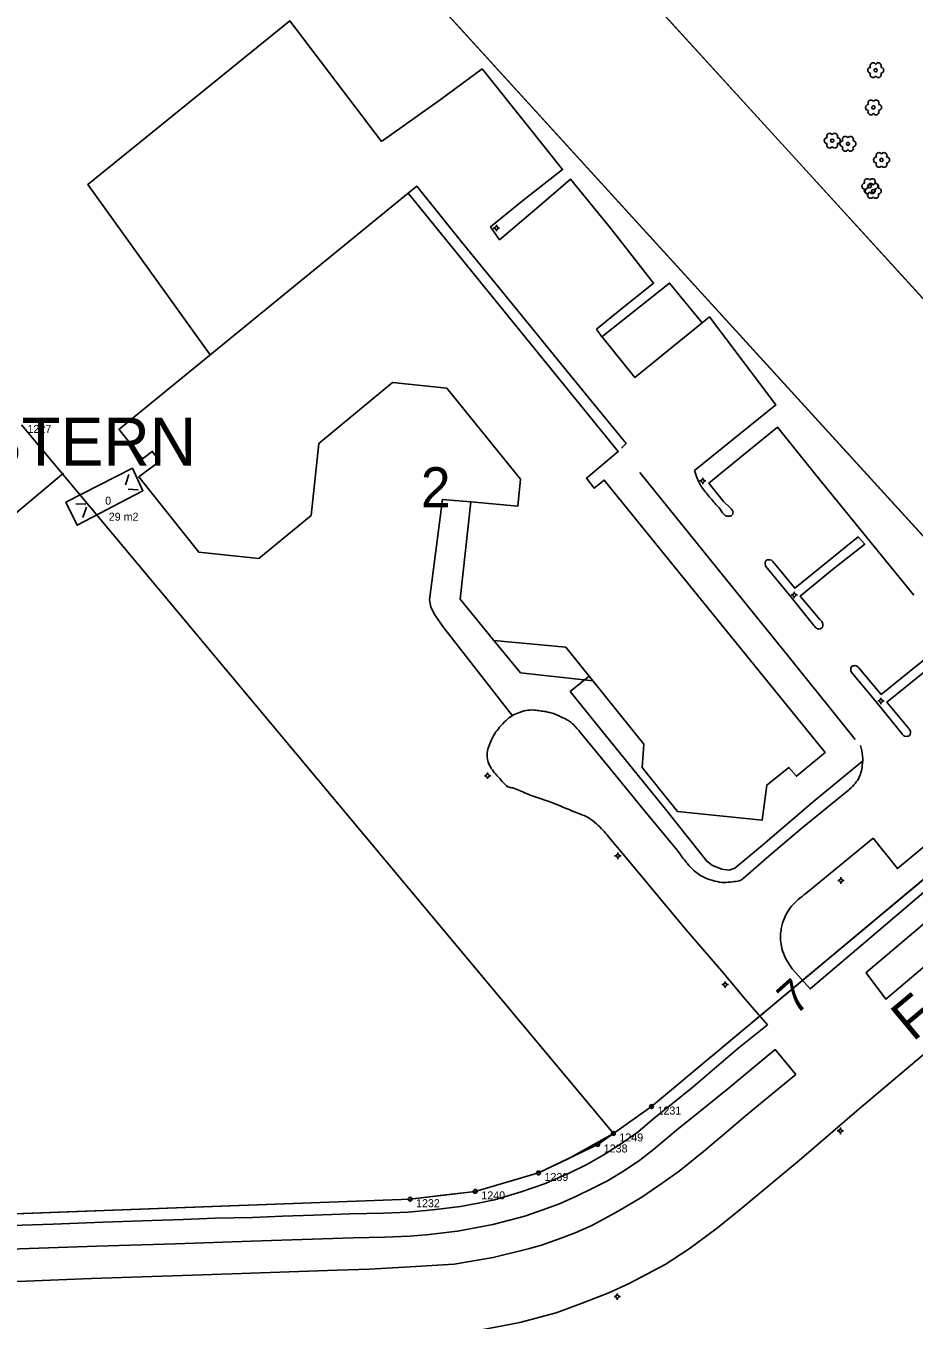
# Model space of a CAD drawing. Extents: x 1517478 to 1518189, y 6494860 to 6495389.
# Drawn here: x 1517920.3 to 1518031.3, y 6494945.7 to 6495107.4 of the extents above; entities that cross this region are included whole.
import ezdxf

# ---------------------------------------------------------------- set-up
doc = ezdxf.new("R2010")
doc.units = 0
for name, color, linetype in [('adress', 7, 'Continuous'), ('allmanbygg_symbollinje', 7, 'Continuous'), ('allmanbyggnad', 7, 'Continuous'), ('allmanbyggnad_nummer', 7, 'Continuous'), ('byggnad_areatext', 7, 'Continuous'), ('fastighetsbeteckning', 7, 'Continuous'), ('gatunamn', 7, 'Continuous'), ('gc_vag', 7, 'Continuous'), ('grans', 7, 'Continuous'), ('granspunkt', 7, 'Continuous'), ('granspunkt_text', 7, 'Continuous'), ('kvartersgrans', 7, 'Continuous'), ('kvartersgrans_utan_fastgr', 7, 'Continuous'), ('kvartersnamn', 7, 'Continuous'), ('kvartersytor', 7, 'Continuous'), ('lovtrad', 7, 'Continuous'), ('parkeringskant', 7, 'Continuous'), ('planteringskant', 7, 'Continuous'), ('rattighet_grans_ANV_EJ', 7, 'Continuous'), ('stolpe_belysning', 7, 'Continuous'), ('trappa_byggnad', 7, 'Continuous'), ('uthus', 7, 'Continuous'), ('vagkant', 7, 'Continuous'), ('vagkant_mindre', 7, 'Continuous')]:
    doc.layers.add(name, color=color, linetype=linetype)

msp = doc.modelspace()

# ---------------------------------------------------------------- linework, layer by layer
at = {"layer": 'allmanbygg_symbollinje'}
for p, q in [((1517933.16, 6495051.39), (1517932.74, 6495050.08)), ((1517933.04, 6495049.54), (1517934.3, 6495049.48)), ((1517926.51, 6495047.74), (1517927.77, 6495047.68)), ((1517927.83, 6495047.32), (1517927.41, 6495046))]:
    msp.add_line(p, q, dxfattribs=at)
at = {"layer": 'allmanbyggnad'}
for points in [[(1517931.88, 6495057.02), (1517968.08, 6495086.54), (1517994.34, 6495054.25), (1517990.35, 6495050.91), (1517991.33, 6495049.66), (1517992.59, 6495050.68), (1518020.21, 6495016.65), (1518016.6, 6495013.68), (1518015.65, 6495014.78), (1518012.9, 6495012.57), (1518012.33, 6495008.18), (1518001.72, 6495009.28), (1517997.31, 6495014.75), (1517997.53, 6495017.68), (1517987.77, 6495029.81), (1517978.76, 6495030.65), (1517974.55, 6495035.81), (1517975.91, 6495047.99), (1517981.76, 6495047.42), (1517982.09, 6495050.79), (1517972.88, 6495062.16), (1517966.11, 6495062.88), (1517956.9, 6495055.28), (1517955.93, 6495046.27), (1517949.41, 6495040.9), (1517941.88, 6495041.67), (1517934.38, 6495051.09), (1517937.03, 6495053.07), (1517936.06, 6495054.26), (1517934.86, 6495053.33), (1517931.87, 6495057.03)], [(1517925.25, 6495047.92), (1517933.58, 6495052.17), (1517934.9, 6495049.36), (1517926.69, 6495045.04), (1517925.25, 6495047.92)]]:
    msp.add_lwpolyline(points, dxfattribs=at)
at = {"layer": 'gc_vag'}
for points in [[(1517981.09, 6495021.24), (1517972.4, 6495032.38), (1517971.41, 6495033.86), (1517970.92, 6495034.79), (1517970.73, 6495035.72), (1517972.34, 6495048.28), (1517975.91, 6495047.99)], [(1518018.32, 6494987.11), (1518024.97, 6494992.73), (1518033.63, 6495000.09), (1518042.48, 6495007.51), (1518049.18, 6495012.98)], [(1518025.3, 6494989.09), (1518035.06, 6494997.36), (1518042.35, 6495003.28), (1518049.31, 6495009.27)], [(1518013.01, 6494982.59), (1518009.23, 6494979.59), (1518003.7, 6494974.86), (1518000.89, 6494972.62), (1517998.86, 6494970.97), (1517996.76, 6494969.18), (1517994.49, 6494967.61), (1517992.45, 6494966.34)], [(1518004.36, 6494971.67), (1518008.04, 6494974.61), (1518013.96, 6494979.52), (1518016.53, 6494976.42)], [(1517982.65, 6494958.71), (1517984.89, 6494959.48), (1517986.99, 6494960.25), (1517989.2, 6494961.23), (1517991.09, 6494962.14), (1517992.98, 6494963.12), (1517994.98, 6494964.31), (1517997.04, 6494965.71), (1517998.72, 6494967.04), (1518000.05, 6494968.1), (1518001.63, 6494969.43), (1518004.36, 6494971.67)], [(1517992.45, 6494966.34), (1517990.41, 6494965.15), (1517988.2, 6494964.07), (1517985.12, 6494962.73), (1517982.21, 6494961.72), (1517978.86, 6494960.74)], [(1517978.86, 6494960.74), (1517976.83, 6494960.32), (1517974.59, 6494959.9), (1517971.16, 6494959.48), (1517968.08, 6494959.19)], [(1517968.08, 6494959.19), (1517964.98, 6494959.09), (1517960.81, 6494958.98), (1517956.22, 6494958.84), (1517952.37, 6494958.7), (1517948.59, 6494958.53), (1517943.93, 6494958.46), (1517939.93, 6494958.28)], [(1517939.93, 6494958.28), (1517936.05, 6494958.14), (1517929.92, 6494957.93), (1517923.68, 6494957.69), (1517915.87, 6494957.44)], [(1517961.19, 6494956.01), (1517965.13, 6494956.08), (1517968.22, 6494956.22), (1517970.32, 6494956.36), (1517974.24, 6494956.81), (1517978.65, 6494957.65), (1517982.65, 6494958.71)], [(1517938.99, 6494955.23), (1517948.44, 6494955.58), (1517961.19, 6494956.01)], [(1517907.22, 6494954.18), (1517920.7, 6494954.64), (1517929.14, 6494954.95), (1517938.99, 6494955.23)]]:
    msp.add_lwpolyline(points, dxfattribs=at)
at = {"layer": 'grans'}
for p, q in [((1517942.78, 6495142.01), (1518054.69, 6495019.3)), ((1517993.72, 6494969.04), (1517919.72, 6495057.58)), ((1517998.49, 6494972.4), (1518054.69, 6495019.3)), ((1517993.72, 6494969.04), (1517998.49, 6494972.4)), ((1517991.77, 6494967.66), (1517993.72, 6494969.04)), ((1517984.36, 6494964.1), (1517991.77, 6494967.66)), ((1517976.46, 6494961.8), (1517984.36, 6494964.1)), ((1517845.48, 6494956.3), (1517968.3, 6494960.82)), ((1517968.3, 6494960.82), (1517976.46, 6494961.8))]:
    msp.add_line(p, q, dxfattribs=at)
at = {"layer": 'granspunkt'}
for centre in [(1517998.49, 6494972.4), (1517993.72, 6494969.04), (1517991.77, 6494967.66), (1517984.36, 6494964.1), (1517968.3, 6494960.82), (1517976.46, 6494961.8)]:
    msp.add_circle(centre, 0.237, dxfattribs=at)
at = {"layer": 'kvartersgrans'}
msp.add_line((1517998.49, 6494972.4), (1518054.69, 6495019.3), dxfattribs=at)
for points in [[(1517905.68, 6495182.68), (1517942.78, 6495142.01), (1518054.69, 6495019.3)], [(1517991.77, 6494967.66), (1517993.72, 6494969.04), (1517998.49, 6494972.4)], [(1517810.53, 6494961.99), (1517821.9, 6494958.56), (1517833.61, 6494956.65), (1517845.48, 6494956.3), (1517968.3, 6494960.82), (1517976.46, 6494961.8), (1517984.36, 6494964.1), (1517991.77, 6494967.66)]]:
    msp.add_lwpolyline(points, dxfattribs=at)
at = {"layer": 'kvartersgrans_utan_fastgr'}
msp.add_line((1517921.04, 6495195.52), (1518074.11, 6495027.69), dxfattribs=at)
at = {"layer": 'kvartersytor'}
for points in [[(1518119.61, 6495108.06), (1518120.35, 6495105.08), (1518120.04, 6495097.16), (1518117.91, 6495084.51), (1518115.77, 6495071.86), (1518114.98, 6495068.27), (1518113.39, 6495063.98), (1518112.21, 6495061.91), (1518110.29, 6495058.89), (1518107.91, 6495056.05), (1518105.41, 6495053.81), (1518074.11, 6495027.69), (1517921.04, 6495195.52)], [(1517905.68, 6495182.68), (1518054.69, 6495019.3), (1517998.49, 6494972.4), (1517993.72, 6494969.04), (1517988.06, 6494965.88), (1517984.36, 6494964.1), (1517976.46, 6494961.8), (1517972.38, 6494961.31), (1517968.3, 6494960.82), (1517845.48, 6494956.3), (1517833.61, 6494956.65)]]:
    msp.add_lwpolyline(points, dxfattribs=at)
at = {"layer": 'lovtrad'}
for centre in [(1518026.52, 6495101.91), (1518026.24, 6495097.26), (1518021.09, 6495093.11), (1518023.05, 6495092.71), (1518027.25, 6495090.7), (1518025.78, 6495087.42), (1518026.2, 6495086.82)]:
    msp.add_circle(centre, 0.2, dxfattribs=at)
for centre, start, end in [((1518025.89, 6495101.9), 89.5389, 268.9887), ((1518026.2, 6495102.46), 29.1347, 212.3057), ((1518026.2, 6495101.36), 150.5831, 330.865), ((1518026.84, 6495102.46), 329.1331, 150.8613), ((1518026.84, 6495101.36), 209.1844, 30.8583), ((1518027.16, 6495101.91), 269.1508, 90.8733), ((1518025.92, 6495097.81), 29.1347, 212.3057), ((1518026.56, 6495097.81), 329.1331, 150.8613), ((1518025.61, 6495097.25), 89.5389, 268.9887), ((1518025.92, 6495096.7), 150.5831, 330.865), ((1518026.56, 6495096.7), 209.1844, 30.8583), ((1518026.88, 6495097.26), 269.1508, 90.8733), ((1518020.45, 6495093.1), 89.5389, 268.9887), ((1518020.77, 6495093.66), 29.1347, 212.3057), ((1518021.4, 6495093.66), 329.1331, 150.8613), ((1518021.72, 6495093.11), 269.1508, 90.8733), ((1518022.73, 6495093.27), 29.1347, 212.3057), ((1518023.37, 6495093.27), 329.1331, 150.8613), ((1518020.77, 6495092.55), 150.5831, 330.865), ((1518021.4, 6495092.55), 209.1844, 30.8583), ((1518022.42, 6495092.71), 89.5389, 268.9887), ((1518022.73, 6495092.16), 150.5831, 330.865), ((1518023.37, 6495092.16), 209.1844, 30.8583), ((1518023.69, 6495092.71), 269.1508, 90.8733), ((1518026.93, 6495091.25), 29.1347, 212.3057), ((1518027.57, 6495091.25), 329.1331, 150.8613), ((1518026.62, 6495090.69), 89.5389, 268.9887), ((1518026.93, 6495090.14), 150.5831, 330.865), ((1518027.57, 6495090.14), 209.1844, 30.8583), ((1518027.89, 6495090.7), 269.1508, 90.8733), ((1518025.46, 6495087.98), 29.1347, 212.3057), ((1518026.1, 6495087.98), 329.1331, 150.8613), ((1518025.15, 6495087.42), 89.5389, 268.9887), ((1518025.46, 6495086.87), 150.5831, 330.865), ((1518025.57, 6495086.81), 89.5389, 268.9887), ((1518025.88, 6495087.38), 29.1347, 212.3057), ((1518026.1, 6495086.87), 209.1844, 30.8583), ((1518026.52, 6495087.38), 329.1331, 150.8613), ((1518026.42, 6495087.42), 269.1508, 90.8733), ((1518026.84, 6495086.82), 269.1508, 90.8733), ((1518025.88, 6495086.27), 150.5831, 330.865), ((1518026.52, 6495086.27), 209.1844, 30.8583)]:
    msp.add_arc(centre, 0.366, start, end, dxfattribs=at)
at = {"layer": 'parkeringskant'}
msp.add_line((1517991.6, 6495069.53), (1517992.29, 6495068.6), dxfattribs=at)
for points in [[(1517964.72, 6495092.99), (1517953.28, 6495108.07), (1517928.01, 6495087.61), (1517943.33, 6495066.36)], [(1517964.72, 6495092.99), (1517972.07, 6495098.22), (1517977.31, 6495102.07), (1517983.13, 6495094.84), (1517987.38, 6495089.5), (1517982.34, 6495085.57), (1517978.37, 6495082.32), (1517979.49, 6495080.73), (1517984.46, 6495084.9), (1517988.37, 6495088.28), (1517993.4, 6495082.12), (1517998.74, 6495075.31), (1517994.53, 6495071.92), (1517991.6, 6495069.53)], [(1517994.73, 6495054.69), (1517995.32, 6495055.28), (1517988.37, 6495063.76), (1517982.21, 6495071.32), (1517974.72, 6495080.46), (1517969.13, 6495087.4), (1517968.08, 6495086.54)], [(1518003.87, 6495051.87), (1518014.03, 6495060.08), (1518005.76, 6495071.07), (1518004.81, 6495070.32)], [(1518031.29, 6495036.3), (1518025.43, 6495043.52), (1518019, 6495051.38), (1518014.23, 6495057.31), (1518009.99, 6495053.83), (1518005.66, 6495050.31), (1518007.51, 6495048), (1518008.31, 6495047.2)], [(1518016.35, 6495027.72), (1518007.68, 6495038.45), (1517997.01, 6495051.64)], [(1518019.55, 6495033.25), (1518017.07, 6495036.17), (1518021.07, 6495039.48), (1518025.15, 6495042.66), (1518024.32, 6495043.59), (1518016.4, 6495037.16), (1518013.66, 6495040.51)], [(1518018.79, 6495032.52), (1518015.94, 6495036.07), (1518012.79, 6495039.88)], [(1518030.63, 6495019.67), (1518027.91, 6495022.92), (1518031.59, 6495025.9), (1518035.89, 6495029.34), (1518035.13, 6495030.27), (1518030.69, 6495026.73), (1518027.22, 6495023.88), (1518024.37, 6495027.26)], [(1518029.77, 6495019.01), (1518026.75, 6495022.75), (1518023.47, 6495026.73)], [(1518026.19, 6495005.95), (1518029.24, 6495002.14), (1518037.78, 6495009.23), (1518035.4, 6495012.08)]]:
    msp.add_lwpolyline(points, dxfattribs=at)
for points in [[(1518003.87, 6495051.87), (1518004.2, 6495050.91), (1518004.56, 6495050.15), (1518005.49, 6495048.89), (1518006.55, 6495047.63), (1518007.21, 6495046.84), (1518007.58, 6495046.37), (1518008.01, 6495046.17), (1518008.44, 6495046.24), (1518008.64, 6495046.44), (1518008.64, 6495046.84), (1518008.31, 6495047.2)], [(1518012.79, 6495039.88), (1518012.7, 6495040.18), (1518012.75, 6495040.5), (1518012.87, 6495040.67), (1518013.17, 6495040.73), (1518013.48, 6495040.66), (1518013.66, 6495040.51)], [(1518018.79, 6495032.52), (1518019.26, 6495032.1), (1518019.67, 6495032.13), (1518019.88, 6495032.32), (1518019.92, 6495032.63), (1518019.78, 6495033), (1518019.55, 6495033.25)], [(1518023.47, 6495026.73), (1518023.41, 6495026.98), (1518023.46, 6495027.28), (1518023.56, 6495027.44), (1518023.83, 6495027.49), (1518024.09, 6495027.49), (1518024.24, 6495027.38), (1518024.37, 6495027.26)], [(1518029.77, 6495019.01), (1518030.14, 6495018.68), (1518030.48, 6495018.67), (1518030.74, 6495018.77), (1518030.87, 6495019.04), (1518030.88, 6495019.29), (1518030.76, 6495019.5), (1518030.63, 6495019.67)]]:
    msp.add_spline(points, degree=3, dxfattribs=at)
at = {"layer": 'planteringskant'}
msp.add_line((1517990.69, 6495026.18), (1517988.32, 6495024.26), dxfattribs=at)
for points in [[(1517988.32, 6495024.26), (1517993.4, 6495017.96), (1518000.23, 6495009.56), (1518004.46, 6495004.29)], [(1518004.46, 6495004.29), (1518005.4, 6495003.05), (1518006.12, 6495002.53), (1518007.29, 6495002.07), (1518008.2, 6495001.94), (1518008.92, 6495002.2), (1518012.11, 6495004.87), (1518018.74, 6495010.54), (1518024.86, 6495015.55)]]:
    msp.add_lwpolyline(points, dxfattribs=at)
at = {"layer": 'rattighet_grans_ANV_EJ'}
msp.add_line((1517924.99, 6495051.56), (1517819.73, 6494963.58), dxfattribs=at)
at = {"layer": 'stolpe_belysning'}
for p, q in [((1517978.9, 6495082.19), (1517978.7, 6495082.19)), ((1517979.1, 6495082.39), (1517979.1, 6495082.59)), ((1517979.1, 6495081.99), (1517979.1, 6495081.79)), ((1517979.3, 6495082.19), (1517979.5, 6495082.19)), ((1518004.69, 6495050.58), (1518004.49, 6495050.58)), ((1518004.89, 6495050.78), (1518004.89, 6495050.98)), ((1518004.89, 6495050.38), (1518004.89, 6495050.18)), ((1518005.09, 6495050.58), (1518005.29, 6495050.58)), ((1518016.34, 6495036.53), (1518016.34, 6495036.73)), ((1518016.14, 6495036.33), (1518015.94, 6495036.33)), ((1518016.34, 6495036.13), (1518016.34, 6495035.93)), ((1518016.54, 6495036.33), (1518016.74, 6495036.33)), ((1518026.98, 6495023.08), (1518026.78, 6495023.08)), ((1518027.18, 6495023.28), (1518027.18, 6495023.48)), ((1518027.18, 6495022.88), (1518027.18, 6495022.68)), ((1518027.38, 6495023.08), (1518027.58, 6495023.08)), ((1517977.99, 6495013.94), (1517977.99, 6495014.14)), ((1517977.79, 6495013.74), (1517977.59, 6495013.74)), ((1517977.99, 6495013.54), (1517977.99, 6495013.34)), ((1517978.19, 6495013.74), (1517978.39, 6495013.74)), ((1517994.08, 6495003.73), (1517993.88, 6495003.73)), ((1517994.28, 6495003.93), (1517994.28, 6495004.13)), ((1517994.28, 6495003.53), (1517994.28, 6495003.33)), ((1517994.48, 6495003.73), (1517994.68, 6495003.73)), ((1518022.17, 6495000.85), (1518022.17, 6495001.05)), ((1518021.97, 6495000.65), (1518021.77, 6495000.65)), ((1518022.17, 6495000.45), (1518022.17, 6495000.25)), ((1518022.37, 6495000.65), (1518022.57, 6495000.65)), ((1518007.7, 6494987.83), (1518007.7, 6494988.03)), ((1518007.5, 6494987.63), (1518007.3, 6494987.63)), ((1518007.7, 6494987.43), (1518007.7, 6494987.23)), ((1518007.9, 6494987.63), (1518008.1, 6494987.63)), ((1518021.9, 6494969.36), (1518021.7, 6494969.36)), ((1518022.1, 6494969.56), (1518022.1, 6494969.76)), ((1518022.1, 6494969.16), (1518022.1, 6494968.96)), ((1518022.3, 6494969.36), (1518022.5, 6494969.36)), ((1517994.01, 6494948.64), (1517993.81, 6494948.64)), ((1517994.21, 6494948.84), (1517994.21, 6494949.04)), ((1517994.21, 6494948.44), (1517994.21, 6494948.24)), ((1517994.41, 6494948.64), (1517994.61, 6494948.64))]:
    msp.add_line(p, q, dxfattribs=at)
for centre in [(1517979.1, 6495082.19), (1518004.89, 6495050.58), (1518016.34, 6495036.33), (1518027.18, 6495023.08), (1517977.99, 6495013.74), (1517994.28, 6495003.73), (1518022.17, 6495000.65), (1518007.7, 6494987.63), (1518022.1, 6494969.36), (1517994.21, 6494948.64)]:
    msp.add_circle(centre, 0.2, dxfattribs=at)
at = {"layer": 'trappa_byggnad'}
msp.add_lwpolyline([(1517978.79, 6495030.64), (1517982.12, 6495026.61), (1517991.15, 6495025.61)], dxfattribs=at)
at = {"layer": 'uthus'}
msp.add_lwpolyline([(1517992.29, 6495068.6), (1518000.76, 6495075.3), (1518004.81, 6495070.32), (1517996.42, 6495063.51), (1517992.27, 6495068.63)], dxfattribs=at)
at = {"layer": 'vagkant'}
for points in [[(1518025.31, 6494989.09), (1518027.77, 6494985.83), (1518036.75, 6494993.39), (1518044.89, 6495000.16), (1518051.52, 6495005.62), (1518056.86, 6495010.05)], [(1518052.14, 6494995.27), (1518041.28, 6494986.3), (1518033.54, 6494979.77), (1518024.45, 6494972.11)], [(1518009.97, 6494970.97), (1518013.08, 6494973.56), (1518016.53, 6494976.42)], [(1518024.45, 6494972.11), (1518017.25, 6494965.92), (1518009.56, 6494959.53)], [(1517983.24, 6494954.64), (1517984.75, 6494955.06), (1517987.09, 6494955.9), (1517988.95, 6494956.6), (1517991.02, 6494957.55), (1517992.56, 6494958.35), (1517994.34, 6494959.34), (1517997.29, 6494961.09), (1517999.81, 6494962.81), (1518001.95, 6494964.31), (1518004.99, 6494966.77), (1518008.14, 6494969.43), (1518009.97, 6494970.97)], [(1518009.56, 6494959.53), (1518006.76, 6494957.23), (1518003.19, 6494954.61), (1518000.18, 6494952.64), (1517995.69, 6494950.3)], [(1517959.2, 6494951.94), (1517963.24, 6494952.08), (1517967.62, 6494952.33), (1517973.82, 6494952.71), (1517978.69, 6494953.52), (1517983.24, 6494954.64)], [(1517907.64, 6494950.12), (1517920.28, 6494950.57), (1517928.48, 6494950.89), (1517939.83, 6494951.27)], [(1517939.83, 6494951.27), (1517946.03, 6494951.48), (1517959.2, 6494951.94)], [(1517995.69, 6494950.3), (1517993.15, 6494949.1), (1517989.83, 6494947.81), (1517986.57, 6494946.62), (1517982.02, 6494945.42), (1517977.25, 6494944.51), (1517973.02, 6494944.09), (1517968.67, 6494943.71)]]:
    msp.add_lwpolyline(points, dxfattribs=at)
at = {"layer": 'vagkant_mindre'}
for p, q in [((1518026.19, 6495005.95), (1518017.78, 6494999.03)), ((1518002.79, 6494994.52), (1518007.28, 6494989.32)), ((1518016.08, 6494989.62), (1518018.36, 6494987.07))]:
    msp.add_line(p, q, dxfattribs=at)
for points in [[(1518016.11, 6495028.02), (1518020.6, 6495022.42), (1518023.95, 6495018.28)], [(1517989.53, 6495019.24), (1517993.21, 6495014.76), (1517997.64, 6495009.33), (1518001.68, 6495004.43)], [(1518023.11, 6495011.92), (1518017.32, 6495007.24), (1518013.51, 6495003.96), (1518009.97, 6495000.91)], [(1517992.94, 6495006.33), (1517996, 6495002.67), (1518002.79, 6494994.52)], [(1518007.28, 6494989.32), (1518010.26, 6494985.77), (1518013.01, 6494982.59)]]:
    msp.add_lwpolyline(points, dxfattribs=at)
for points in [[(1517978.2, 6495015.12), (1517977.94, 6495016.05), (1517978.04, 6495017.08), (1517978.37, 6495017.94), (1517978.9, 6495019), (1517979.5, 6495019.8), (1517980.32, 6495020.66), (1517981.05, 6495021.22), (1517981.88, 6495021.62), (1517982.81, 6495021.89), (1517983.8, 6495021.95), (1517984.56, 6495021.85), (1517985.23, 6495021.75), (1517986.35, 6495021.46), (1517987.31, 6495021.03), (1517988.11, 6495020.63), (1517988.47, 6495020.36), (1517989.03, 6495019.8), (1517989.53, 6495019.24)], [(1518023.08, 6495011.89), (1518024.36, 6495013.37), (1518024.84, 6495015), (1518024.88, 6495016.2), (1518024.62, 6495017.5)], [(1517993.09, 6495006.18), (1517991.63, 6495007.71), (1517990.57, 6495008.5), (1517989.18, 6495009.1), (1517987.39, 6495009.83), (1517984.81, 6495010.82), (1517982.84, 6495011.52), (1517981.12, 6495012.21), (1517980.57, 6495012.35), (1517979.83, 6495013.04), (1517978.59, 6495014.46), (1517978.12, 6495015.26)], [(1518001.68, 6495004.43), (1518002.73, 6495003.07), (1518003.66, 6495002.01), (1518005.05, 6495001.05), (1518006.4, 6495000.58), (1518007.56, 6495000.39), (1518008.62, 6495000.49), (1518009.48, 6495000.62), (1518009.98, 6495000.92), (1518010.31, 6495001.25)], [(1518017.78, 6494999.03), (1518016.01, 6494997.44), (1518015.11, 6494995.95), (1518014.72, 6494994.65), (1518014.65, 6494992.96), (1518014.88, 6494991.87), (1518015.41, 6494990.65), (1518016.08, 6494989.62)]]:
    msp.add_spline(points, degree=3, dxfattribs=at)

# ---------------------------------------------------------------- texts
at = {"layer": 'adress'}
msp.add_text('7', height=4, rotation=42.0101, dxfattribs=at).set_placement((1518016.48, 6494983.7))
at = {"layer": 'allmanbyggnad_nummer'}
msp.add_text('0', height=1, dxfattribs=at).set_placement((1517930.19, 6495047.61))
at = {"layer": 'byggnad_areatext'}
msp.add_text('29 m2', height=1, dxfattribs=at).set_placement((1517930.63, 6495045.61))
at = {"layer": 'fastighetsbeteckning'}
msp.add_text('2', height=5, rotation=0.0021, dxfattribs=at).set_placement((1517969.65, 6495047.29))
at = {"layer": 'gatunamn'}
msp.add_text('Folkborgsvägen', height=5, rotation=39.8263, dxfattribs=at).set_placement((1518031.17, 6494980.42))
at = {"layer": 'granspunkt_text'}
for s, p in [('1227', (1517920.47, 6495056.58)), ('1231', (1517999.24, 6494971.4)), ('1249', (1517994.47, 6494968.04)), ('1238', (1517992.52, 6494966.66)), ('1239', (1517985.11, 6494963.1)), ('1232', (1517969.05, 6494959.82)), ('1240', (1517977.21, 6494960.8))]:
    msp.add_text(s, height=1, dxfattribs=at).set_placement(p)
at = {"layer": 'kvartersnamn'}
msp.add_text('ORKESTERN', height=6, rotation=0.0021, dxfattribs=at).set_placement((1517891.62, 6495052.48))

doc.saveas('drawing.dxf')
